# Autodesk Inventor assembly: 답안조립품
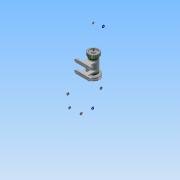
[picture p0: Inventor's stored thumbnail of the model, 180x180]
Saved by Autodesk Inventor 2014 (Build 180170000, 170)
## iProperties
Created: 2015-11
Part Number: 답안조립품
Document SubType Name: Assembly
Designer: 106-16
Author: 106-16
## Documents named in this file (16)
- C:\Users\106-16\Desktop\451110V1015\답안조립품.iam
- C:\Users\106-16\Desktop\451110V1015\1-본체.ipt
- C:\Users\106-16\Desktop\451110V1015\V벨트풀리.ipt
- C:\Users\106-16\Desktop\451110V1015\너트 M 8.ipt
- C:\Users\106-16\Desktop\451110V1015\니플 M 6 x 0.75.ipt
- C:\Users\106-16\Desktop\451110V1015\베어링 15 x 32 x 9.ipt
- C:\Users\106-16\Desktop\451110V1015\볼트 M 6 x 8.ipt
- C:\Users\106-16\Desktop\451110V1015\볼트 M4 x 12.ipt
- C:\Users\106-16\Desktop\451110V1015\스퍼기어.ipt
- C:\Users\106-16\Desktop\451110V1015\스프링와셔 8.ipt
- C:\Users\106-16\Desktop\451110V1015\오일 실 15 25 7.ipt
- C:\Users\106-16\Desktop\451110V1015\와셔 6x11.5.ipt
- C:\Users\106-16\Desktop\451110V1015\와셔 8x17.ipt
- C:\Users\106-16\Desktop\451110V1015\축.ipt
- C:\Users\106-16\Desktop\451110V1015\커버.ipt
- C:\Users\106-16\Desktop\451110V1015\키 3 x 3 x 12.ipt
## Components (12 placed, 4 different names)
1. 1-본체:1
2. V벨트풀리:1
3. KS B 2023 6002 - 15 x 32 x 9:1
4. KS B 2023 6002 - 15 x 32 x 9:2
5. ISO 4762 M4 x 12:2
6. ISO 4762 M4 x 12:3
7. ISO 4762 M4 x 12:4
8. ISO 4762 M4 x 12:5
9. ISO 4762 M4 x 12:1
10. ISO 4762 M4 x 12:6
11. ISO 4762 M4 x 12:7
12. ISO 4762 M4 x 12:8
## Named parameters: d8_d6 = 0, d9_d7 = 0
